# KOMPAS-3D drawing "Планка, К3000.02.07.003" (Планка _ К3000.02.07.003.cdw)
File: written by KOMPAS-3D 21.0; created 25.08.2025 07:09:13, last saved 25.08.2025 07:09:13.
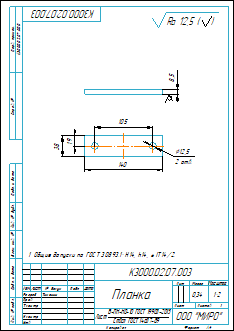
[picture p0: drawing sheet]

Sheet 1: A4, portrait

Document properties: Автор: Lutik; Полное имя файла: C:\Users\Lutik\Yandex.Disk\Документы\Новая папка\Бабка задняя\2D\Плита_К3000.02.07.000\Планка _ К3000.02.07.003.cdw; Знак неуказанной шероховатости: 4; Параметр неуказанной шероховатости: Ra 12,5; Масса: 0.3386

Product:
- Part/product: Планка  | designation К3000.02.07.003
    Материал: Лист$dБ-ПН-НО-10 ГОСТ 19903-2015;Ст3сп ГОСТ 14637-89$ (density 7850 kg/m3)
    Масса: 0.3386

Title block, sheet 1: Наименование: Планка; designation: К3000.02.07.003; Материал: Лист Б-ПН-НО-10 ГОСТ 19903-2015 Ст3сп ГОСТ 14637-89; Масса: 0,34; Количество листов документа: 1; organisation: ООО "МИРО"; Форматы листов документа: A4; Разработал: Тимонин

Views: Вид 1, Слева, Проекционный вид 2
Referenced files in C:\Users\Lutik\Yandex.Disk\Документы\Новая папка\Бабка задняя\3D\: Планка_54.m3d
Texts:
  Ra 12,5
  Ra 12,5 ( )
  К3000.02.07.003 Планка
Dimensions and other numbers on the sheet: 38; 19; 140; 105; 12,5; 2 отв.; 8,5; 1:2; 1; 0,34

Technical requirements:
  Общие допуски по ГОСТ 30893.1: Н14, h14, ± IT14/2.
